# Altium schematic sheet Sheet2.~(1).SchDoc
size A4
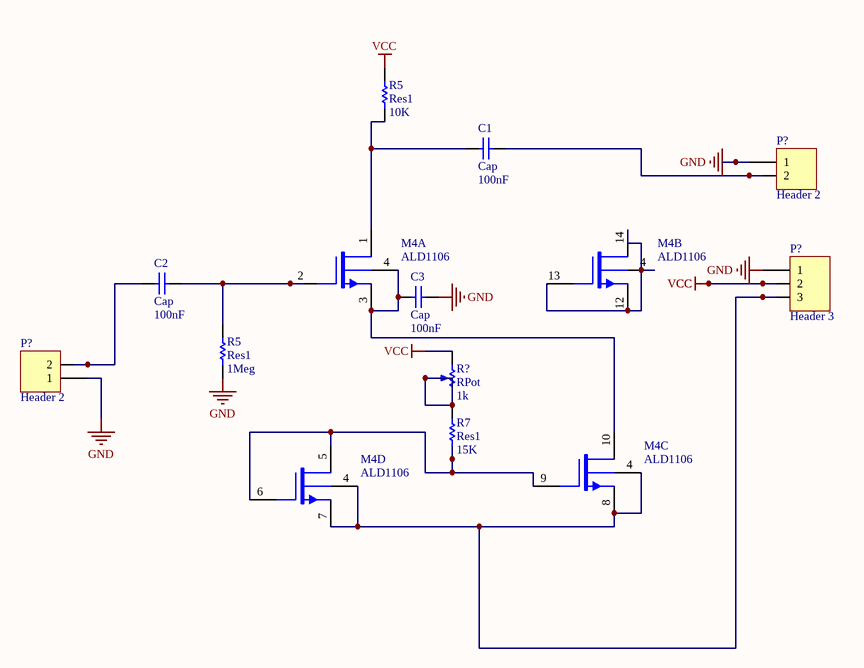
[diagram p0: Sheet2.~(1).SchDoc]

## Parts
(Parts that share a designator on the sheet are numbered #1, #2 ... from top to bottom, then left to right.)
C1  Cap  value 100nF  [RAD-0.3]
C2  Cap  value 100nF  [RAD-0.3]
C3  Cap  value 100nF  [RAD-0.3]
M4  ALD1106  [DIP-14]  (parts A,B,C,D of 4)
P?#1  Header 2  [HDR1X2]
P?#2  Header 3  [HDR1X3]
P?#3  Header 2  [HDR1X2]
R5#1  Res1  value 10K  [AXIAL-0.3]
R5#2  Res1  value 1Meg  [AXIAL-0.3]
R7  Res1  value 15K  [AXIAL-0.3]
R?  RPot  value 1k  [VR5]

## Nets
GND: C3.2 P?#1.1 P?#2.1 P?#3.1 R5#2.1
VCC: P?#2.2 R5#1.2 R?.1(TOP)
NetC1_1: C1.1 M4.1(DN1) R5#1.1
NetC1_2: C1.2 P?#1.2
NetC2_1: C2.1 P?#3.2
NetC2_2: C2.2 M4.2(GN1) R5#2.2
NetC3_1: C3.1 M4.3(SN1) M4.4(V-) M4.10(DN3)
NetM4_4: M4.4(V-) M4.12(SN2) M4.13(GN2) M4.14(DN2)
NetM4_4: M4.4(V-) M4.7(SN4) M4.8(SN3) P?#2.3  [a separate net that carries the same name]
NetM4_5: M4.5(DN4) M4.6(GN4) M4.9(GN3) R7.1
NetR7_2: R7.2 R?.2(TAP) R?.3(BOT)

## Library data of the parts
C1-C3 = Cap: Capacitor
M4 = ALD1106: Quad N-channel matched MOSFET array
P?#1 P?#3 = Header 2: Header, 2-Pin
P?#2 = Header 3: Header, 3-Pin
R5#1 R5#2 R7 = Res1: Resistor
R? = RPot: Potentiometer; Sim Note: Enter the Resistance value and the set point into parameter fields.; Set Position: 0.5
